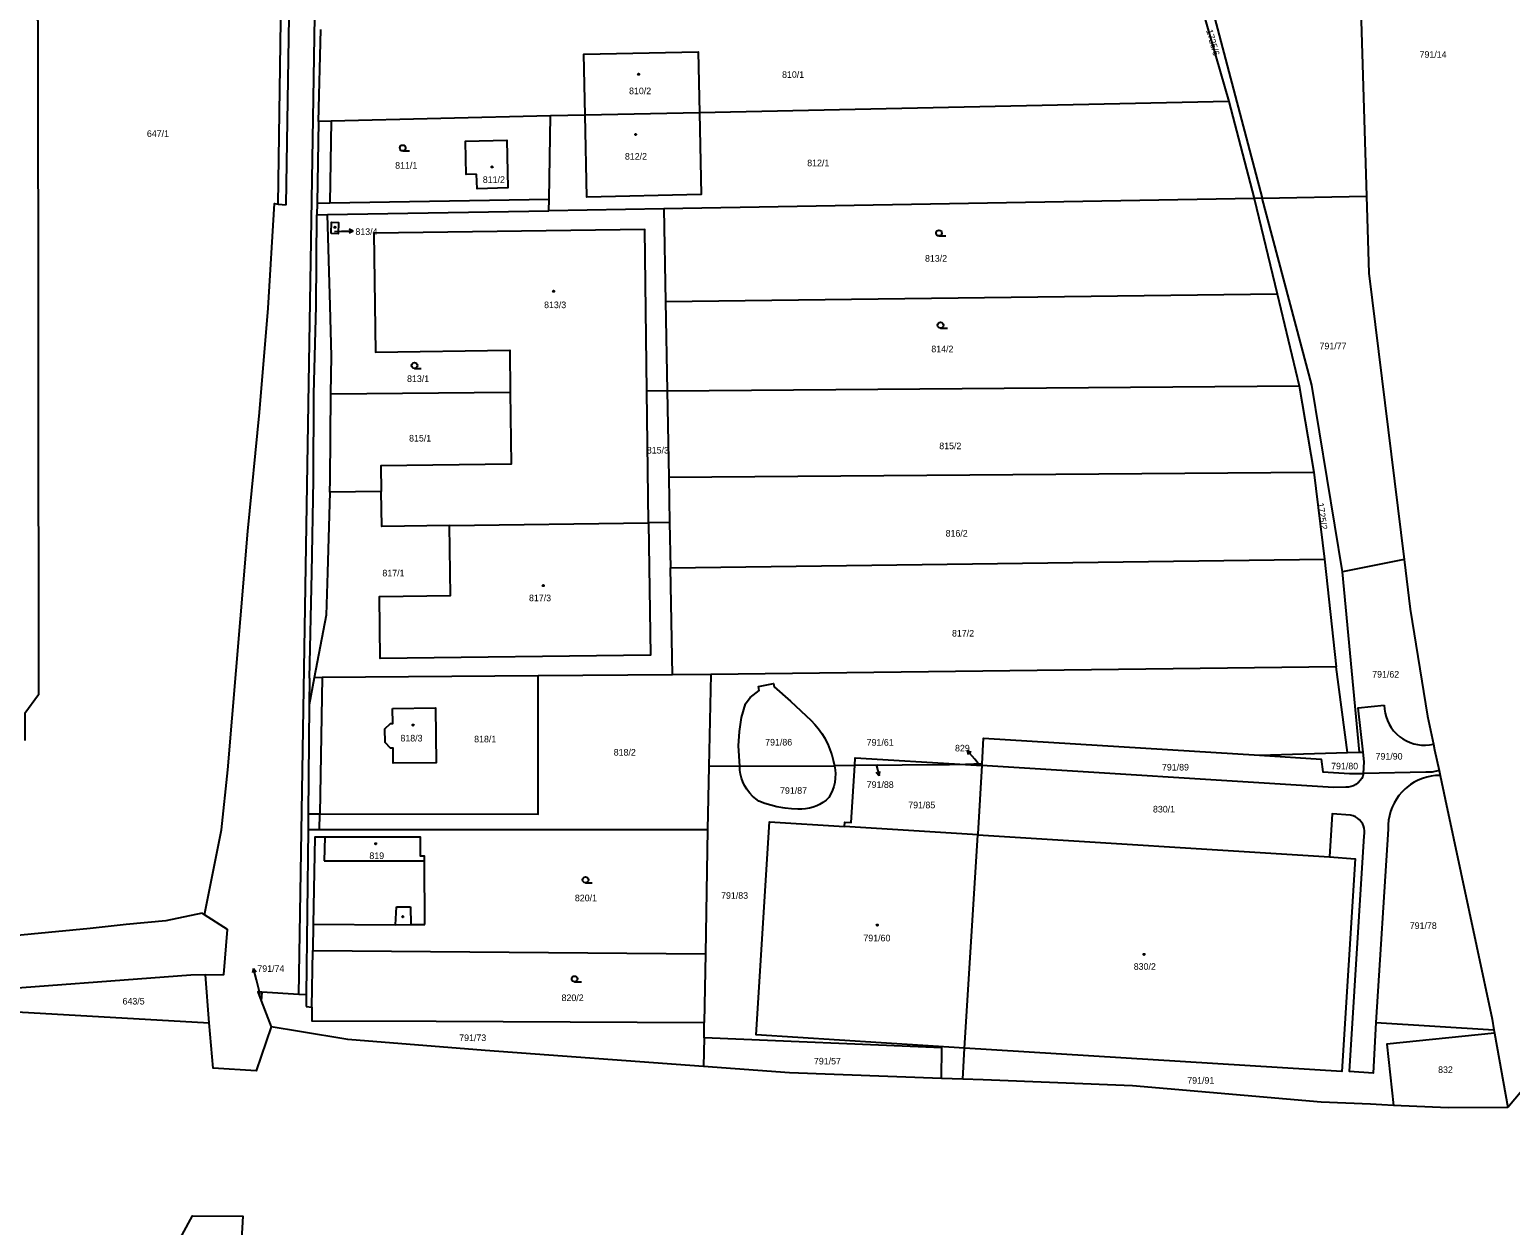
# Model space of a CAD drawing. Extents: x -724107 to -720612, y -1045267 to -1038441.
# Drawn here: x -722617.2 to -722235.9, y -1041870.1 to -1041562.1 of the extents above; entities that cross this region are included whole.
import ezdxf

# ---------------------------------------------------------------- set-up
doc = ezdxf.new("R2010")
doc.units = 0
for name, color, linetype in [('Hranice parcel', 7, 'Continuous'), ('Parcelní čísla', 7, 'Continuous'), ('Pop  PČ popisy', 7, 'Continuous'), ('Vnitřní kresba', 7, 'Continuous'), ('Značky budov', 7, 'Continuous'), ('Značky kultur', 7, 'Continuous')]:
    doc.layers.add(name, color=color, linetype=linetype)

msp = doc.modelspace()

# ---------------------------------------------------------------- linework, layer by layer
at = {"layer": 'Hranice parcel'}
for p, q in [((-722315.07, -1041557.42), (-722308.33, -1041580.65)), ((-722312.48, -1041557.37), (-722299.74, -1041605.52)), ((-722542.76, -1041585.75), (-722542.2, -1041562.06)), ((-722444.69, -1041583.5), (-722474.12, -1041584.11)), ((-722308.33, -1041580.65), (-722444.69, -1041583.5)), ((-722308.33, -1041580.65), (-722301.81, -1041605.56)), ((-722474.12, -1041584.11), (-722483.09, -1041584.3)), ((-722301.81, -1041605.56), (-722453.83, -1041608.27)), ((-722299.74, -1041605.52), (-722301.81, -1041605.56)), ((-722301.81, -1041605.56), (-722295.91, -1041630.17)), ((-722299.74, -1041605.52), (-722272.9, -1041605.04)), ((-722540.46, -1041609.74), (-722483.46, -1041608.8)), ((-722453.83, -1041608.27), (-722483.46, -1041608.8)), ((-722453.83, -1041608.27), (-722453.4, -1041632.16)), ((-722453.4, -1041632.16), (-722295.91, -1041630.17)), ((-722453.4, -1041632.16), (-722452.99, -1041655.19)), ((-722295.91, -1041630.17), (-722290.27, -1041653.85)), ((-722539.65, -1041655.9), (-722493.42, -1041655.52)), ((-722452.99, -1041655.19), (-722458.24, -1041655.23)), ((-722457.8, -1041689.15), (-722458.24, -1041655.23)), ((-722452.99, -1041655.19), (-722290.27, -1041653.85)), ((-722452.99, -1041655.19), (-722452.59, -1041677.4)), ((-722290.27, -1041653.85), (-722286.5, -1041676.06)), ((-722452.59, -1041677.4), (-722286.5, -1041676.06)), ((-722452.59, -1041677.4), (-722452.38, -1041689.08)), ((-722286.5, -1041676.06), (-722283.76, -1041698.49)), ((-722526.64, -1041681.08), (-722539.9, -1041681.26)), ((-722509.08, -1041689.84), (-722457.8, -1041689.15)), ((-722452.38, -1041689.08), (-722457.8, -1041689.15)), ((-722452.38, -1041689.08), (-722452.17, -1041700.77)), ((-722452.17, -1041700.77), (-722283.76, -1041698.49)), ((-722451.67, -1041728.34), (-722452.17, -1041700.77)), ((-722283.76, -1041698.49), (-722280.71, -1041726.24)), ((-722263.22, -1041698.6), (-722279.09, -1041701.81)), ((-722274.75, -1041748.23), (-722279.09, -1041701.81)), ((-722451.67, -1041728.34), (-722486.22, -1041728.6)), ((-722441.75, -1041728.26), (-722451.67, -1041728.34)), ((-722441.75, -1041728.26), (-722442.25, -1041751.9)), ((-722280.71, -1041726.24), (-722441.75, -1041728.26)), ((-722277.82, -1041748.33), (-722280.71, -1041726.24)), ((-722371.92, -1041751.27), (-722376.14, -1041751.4)), ((-722376.14, -1041751.4), (-722371.94, -1041751.66)), ((-722371.94, -1041751.66), (-722371.92, -1041751.27)), ((-722300.49, -1041749.04), (-722277.82, -1041748.33)), ((-722277.82, -1041748.33), (-722274.75, -1041748.23)), ((-722274.75, -1041748.23), (-722273.76, -1041748.2)), ((-722273.48, -1041750.73), (-722273.76, -1041748.2)), ((-722273.66, -1041753.72), (-722273.48, -1041750.73)), ((-722442.25, -1041751.9), (-722442.59, -1041768.19)), ((-722434.31, -1041751.85), (-722442.25, -1041751.9)), ((-722434.31, -1041751.85), (-722409.95, -1041751.71)), ((-722404.69, -1041751.68), (-722409.95, -1041751.71)), ((-722254.24, -1041752.99), (-722253.98, -1041754.22)), ((-722253.98, -1041754.22), (-722252.67, -1041760.31)), ((-722545.43, -1041764.14), (-722545.47, -1041768.15)), ((-722545.47, -1041768.15), (-722545.95, -1041810.78)), ((-722442.59, -1041768.19), (-722443.14, -1041800.17)), ((-722373.04, -1041769.53), (-722407.32, -1041767.39)), ((-722373.04, -1041769.53), (-722282.4, -1041775.2)), ((-722267.33, -1041768.03), (-722270.48, -1041817.83)), ((-722443.14, -1041800.17), (-722443.44, -1041817.83)), ((-722570.93, -1041817.99), (-722571.92, -1041805.59)), ((-722557.35, -1041810.05), (-722557.52, -1041812.28)), ((-722557.52, -1041812.28), (-722554.99, -1041819.01)), ((-722545.95, -1041810.78), (-722545.98, -1041813.71)), ((-722545.98, -1041813.71), (-722544.49, -1041813.88)), ((-722443.51, -1041821.79), (-722443.44, -1041817.83)), ((-722270.48, -1041817.83), (-722240.1, -1041819.75)), ((-722240.1, -1041819.75), (-722239.95, -1041820.6)), ((-722443.51, -1041821.79), (-722443.63, -1041829.2)), ((-722239.95, -1041820.6), (-722236.54, -1041839.78)), ((-722376.9, -1041832.45), (-722376.41, -1041824.46)), ((-722376.9, -1041832.45), (-722382.4, -1041832.25))]:
    msp.add_line(p, q, dxfattribs=at)
for points in [[(-722265.74, -1041433.82), (-722266.73, -1041438.8), (-722270.06, -1041459.03), (-722272.9, -1041484.57), (-722274.08, -1041524.26), (-722274.34, -1041557.03), (-722272.9, -1041605.04)], [(-722618.18, -1041449.99), (-722618.53, -1041555.06), (-722615.08, -1041559.79), (-722614.93, -1041733.5), (-722618.38, -1041738.26), (-722618.4, -1041745.25)], [(-722572.15, -1041790.09), (-722567.78, -1041768.23), (-722566.18, -1041752.78), (-722562.87, -1041713.88), (-722561.01, -1041691.3), (-722557.98, -1041660.77), (-722555.76, -1041633.86), (-722554.15, -1041606.92), (-722553.18, -1041607.03), (-722551.98, -1041524.35)], [(-722474.12, -1041584.11), (-722474.45, -1041568.46), (-722445.02, -1041567.85), (-722444.69, -1041583.5)], [(-722444.69, -1041583.5), (-722444.25, -1041604.59), (-722473.68, -1041605.22), (-722474.12, -1041584.11)], [(-722542.76, -1041585.75), (-722543.17, -1041606.79), (-722543.19, -1041609.79), (-722540.46, -1041609.74)], [(-722483.09, -1041584.3), (-722539.53, -1041585.67), (-722542.76, -1041585.75)], [(-722483.46, -1041608.8), (-722483.36, -1041605.77), (-722483.09, -1041584.3)], [(-722502.08, -1041599.34), (-722504.81, -1041599.39), (-722504.88, -1041595.26), (-722504.96, -1041590.81), (-722494.26, -1041590.57), (-722494.08, -1041602.88), (-722501.97, -1041603.09), (-722502.08, -1041599.34)], [(-722279.09, -1041701.81), (-722287.01, -1041653.65), (-722299.74, -1041605.52)], [(-722272.9, -1041605.04), (-722272.3, -1041624.85), (-722263.22, -1041698.6)], [(-722539.65, -1041655.9), (-722539.47, -1041646.18), (-722539.76, -1041633.25), (-722540.46, -1041609.74)], [(-722539.5, -1041614.63), (-722539.43, -1041611.69), (-722537.67, -1041611.75), (-722537.76, -1041614.68), (-722539.5, -1041614.63)], [(-722458.24, -1041655.23), (-722458.79, -1041613.63), (-722528.52, -1041614.54), (-722528.11, -1041645.16), (-722493.55, -1041644.65), (-722493.42, -1041655.52)], [(-722539.9, -1041681.26), (-722539.81, -1041678.1), (-722539.65, -1041655.9)], [(-722493.42, -1041655.52), (-722493.21, -1041674.06), (-722526.75, -1041674.5), (-722526.64, -1041681.08)], [(-722539.9, -1041681.26), (-722540.52, -1041701.96), (-722540.85, -1041712.96), (-722543.88, -1041729.05)], [(-722509.08, -1041689.84), (-722526.49, -1041690.08), (-722526.64, -1041681.08)], [(-722457.8, -1041689.15), (-722457.31, -1041723.25), (-722526.89, -1041724.1), (-722527.12, -1041708.12), (-722508.84, -1041707.86), (-722509.08, -1041689.84)], [(-722263.22, -1041698.6), (-722261.65, -1041711.4), (-722257.23, -1041738.96), (-722255.69, -1041746.18)], [(-722545.43, -1041764.14), (-722542.47, -1041764.14), (-722486.24, -1041764.17), (-722486.22, -1041728.6)], [(-722486.22, -1041728.6), (-722541.83, -1041729.03), (-722543.88, -1041729.05)], [(-722543.88, -1041729.05), (-722545.19, -1041736.01), (-722545.43, -1041764.14)], [(-722434.31, -1041751.85), (-722434.6, -1041746.62), (-722434.38, -1041742.93), (-722433.87, -1041739.28), (-722432.83, -1041735.75), (-722431.62, -1041734.11), (-722429.31, -1041732.3), (-722429.5, -1041731.27), (-722425.64, -1041730.54), (-722425.48, -1041731.38), (-722421.22, -1041735.09), (-722415.96, -1041740.08)], [(-722273.76, -1041748.2), (-722275.05, -1041736.8), (-722268.34, -1041736.15)], [(-722268.34, -1041736.15), (-722268.28, -1041737.17), (-722268.12, -1041738.17), (-722267.87, -1041739.16), (-722267.52, -1041740.11), (-722267.08, -1041741.03), (-722266.55, -1041741.9), (-722265.93, -1041742.71), (-722265.24, -1041743.46), (-722265.12, -1041743.58), (-722264.35, -1041744.24), (-722263.52, -1041744.83), (-722262.63, -1041745.33), (-722261.7, -1041745.74), (-722260.73, -1041746.06), (-722259.74, -1041746.28), (-722258.73, -1041746.41), (-722257.71, -1041746.43), (-722256.69, -1041746.35), (-722255.69, -1041746.18)], [(-722523.7, -1041736.96), (-722512.69, -1041736.84), (-722512.53, -1041750.96), (-722523.53, -1041751.09), (-722523.61, -1041747.18), (-722524.23, -1041747.17), (-722525.64, -1041745.76), (-722525.72, -1041742.24), (-722524.28, -1041740.85), (-722523.68, -1041740.85), (-722523.7, -1041736.96)], [(-722415.96, -1041740.08), (-722414.96, -1041741.13), (-722414.04, -1041742.24), (-722413.2, -1041743.42), (-722412.44, -1041744.65), (-722412.3, -1041744.9), (-722411.64, -1041746.19), (-722411.08, -1041747.52), (-722410.6, -1041748.89), (-722410.23, -1041750.29), (-722409.95, -1041751.71)], [(-722371.92, -1041751.27), (-722371.51, -1041744.61), (-722300.49, -1041749.04)], [(-722255.69, -1041746.18), (-722255.38, -1041747.63), (-722254.24, -1041752.99)], [(-722404.69, -1041751.68), (-722404.56, -1041749.65), (-722376.14, -1041751.4)], [(-722376.14, -1041751.4), (-722380.32, -1041751.53), (-722404.69, -1041751.68)], [(-722300.49, -1041749.04), (-722284.57, -1041750.03), (-722284.18, -1041753.3), (-722277.31, -1041753.68), (-722275.83, -1041753.76), (-722274.24, -1041753.73), (-722273.66, -1041753.72)], [(-722409.95, -1041751.71), (-722409.78, -1041752.75), (-722409.7, -1041753.8), (-722409.72, -1041754.85), (-722409.73, -1041754.96), (-722409.86, -1041756), (-722410.1, -1041757.03), (-722410.43, -1041758.03), (-722410.85, -1041758.99), (-722411.36, -1041759.91), (-722412.1, -1041760.59), (-722412.91, -1041761.19), (-722413.77, -1041761.71), (-722414.47, -1041762.05), (-722415.41, -1041762.42), (-722416.38, -1041762.68), (-722417.37, -1041762.85), (-722418.37, -1041762.92), (-722419.38, -1041762.89), (-722420.99, -1041762.83), (-722422.59, -1041762.68), (-722423.2, -1041762.59), (-722424.78, -1041762.3), (-722426.34, -1041761.91), (-722427.87, -1041761.42), (-722429.37, -1041760.84), (-722430.21, -1041760.24), (-722431, -1041759.56), (-722431.71, -1041758.81), (-722432.35, -1041757.99), (-722432.53, -1041757.72), (-722433.06, -1041756.83), (-722433.5, -1041755.89), (-722433.85, -1041754.92), (-722434.1, -1041753.91), (-722434.26, -1041752.89), (-722434.31, -1041751.85)], [(-722407.32, -1041767.39), (-722407.26, -1041766.26), (-722405.66, -1041766.38), (-722404.69, -1041751.68)], [(-722371.94, -1041751.66), (-722373.02, -1041769.27), (-722373.04, -1041769.53)], [(-722278.22, -1041757.26), (-722281.43, -1041757.32), (-722371.94, -1041751.66)], [(-722273.66, -1041753.72), (-722273.86, -1041754.37), (-722274.15, -1041754.97), (-722274.53, -1041755.53), (-722274.99, -1041756.03), (-722275.11, -1041756.14), (-722275.65, -1041756.54), (-722276.25, -1041756.86), (-722276.88, -1041757.09), (-722277.55, -1041757.23), (-722278.22, -1041757.26)], [(-722254.24, -1041752.99), (-722256, -1041753.35), (-722257.64, -1041753.41), (-722273.66, -1041753.72)], [(-722253.98, -1041754.22), (-722255.13, -1041754.27), (-722256.28, -1041754.42), (-722257.41, -1041754.67), (-722258.51, -1041755.01), (-722259.58, -1041755.45), (-722260.61, -1041755.98), (-722261.59, -1041756.59), (-722262.51, -1041757.29), (-722262.98, -1041757.71), (-722263.8, -1041758.52), (-722264.55, -1041759.4), (-722265.21, -1041760.35), (-722265.8, -1041761.35), (-722266.29, -1041762.39), (-722266.69, -1041763.47), (-722267, -1041764.59), (-722267.21, -1041765.72), (-722267.32, -1041766.88), (-722267.33, -1041768.03)], [(-722252.67, -1041760.31), (-722240.58, -1041816.98), (-722240.1, -1041819.75)], [(-722376.41, -1041824.46), (-722430.08, -1041821.03), (-722426.65, -1041766.18), (-722407.32, -1041767.39)], [(-722277.01, -1041764.46), (-722281.73, -1041764.15), (-722282.4, -1041775.2)], [(-722273.51, -1041769.82), (-722273.41, -1041769.16), (-722273.41, -1041768.49), (-722273.51, -1041767.84), (-722273.7, -1041767.2), (-722273.9, -1041766.76), (-722274.26, -1041766.2), (-722274.69, -1041765.69), (-722275.19, -1041765.26), (-722275.76, -1041764.9), (-722276.37, -1041764.63), (-722277.01, -1041764.46)], [(-722545.47, -1041768.15), (-722542.54, -1041768.14), (-722442.59, -1041768.19)], [(-722515.43, -1041792.58), (-722515.48, -1041776.23), (-722515.47, -1041774.98), (-722516.51, -1041774.99), (-722516.5, -1041770.13), (-722541.19, -1041770.09), (-722543.75, -1041770.09), (-722544.13, -1041792.57), (-722522.98, -1041792.68), (-722519.05, -1041792.63), (-722515.43, -1041792.58)], [(-722376.41, -1041824.46), (-722376.33, -1041823.18), (-722373.04, -1041769.53)], [(-722270.48, -1041817.83), (-722271.22, -1041830.88), (-722277.29, -1041830.53), (-722273.51, -1041769.82)], [(-722572.15, -1041790.09), (-722572.74, -1041789.71), (-722582.1, -1041791.68), (-722592.36, -1041792.63), (-722601.62, -1041793.62), (-722636.53, -1041797.02), (-722697.04, -1041802.03), (-722736.46, -1041801.53), (-722782.47, -1041798.74), (-722864.18, -1041795.53), (-722887.81, -1041795.13), (-722950.17, -1041789.44), (-722986.65, -1041786.31), (-723038.66, -1041784.3), (-723089.92, -1041782.77), (-723094.54, -1041778.33), (-723095.52, -1041777.18)], [(-722282.4, -1041775.2), (-722275.87, -1041775.67), (-722279.29, -1041830.52), (-722376.41, -1041824.46)], [(-722571.92, -1041805.59), (-722567.17, -1041805.48), (-722566.22, -1041793.95), (-722572.15, -1041790.09)], [(-722544.49, -1041813.88), (-722544.24, -1041799.36), (-722443.14, -1041800.17)], [(-722571.92, -1041805.59), (-722575.67, -1041805.69), (-722633.05, -1041809.97), (-722652.84, -1041811.22), (-722679.23, -1041813.23), (-722679.21, -1041814.75)], [(-722557.35, -1041810.05), (-722558.38, -1041809.98), (-722557.52, -1041812.28)], [(-722545.95, -1041810.78), (-722547.85, -1041810.66), (-722557.35, -1041810.05)], [(-722679.21, -1041814.75), (-722631.41, -1041814.8), (-722620.47, -1041815.12), (-722570.93, -1041817.99)], [(-722544.49, -1041813.88), (-722544.55, -1041817.4), (-722512.51, -1041817.54), (-722443.44, -1041817.83)], [(-722554.99, -1041819.01), (-722558.86, -1041830.28), (-722569.93, -1041829.62), (-722570.93, -1041817.99)], [(-722443.63, -1041829.2), (-722499.89, -1041825.11), (-722535.21, -1041822.28), (-722547.65, -1041820.22), (-722554.99, -1041819.01)], [(-722382.4, -1041832.25), (-722382.31, -1041824.43), (-722443.51, -1041821.79)], [(-722239.95, -1041820.6), (-722267.72, -1041823.45), (-722265.92, -1041839.22)], [(-722382.4, -1041832.25), (-722421.53, -1041830.81), (-722443.63, -1041829.2)], [(-722265.92, -1041839.22), (-722268.96, -1041839.08), (-722271.9, -1041838.94), (-722284.61, -1041838.35), (-722333.14, -1041834.17), (-722371.65, -1041832.64), (-722376.9, -1041832.45)], [(-722214.16, -1041838.45), (-722210.51, -1041854.4), (-722230.06, -1041853.88), (-722232.25, -1041846.67), (-722232.88, -1041835.47), (-722236.54, -1041839.78)], [(-722236.54, -1041839.78), (-722251.92, -1041839.87), (-722265.92, -1041839.22)], [(-722580.09, -1041876.52), (-722575.26, -1041867.66), (-722562.3, -1041867.74), (-722562.79, -1041876.81), (-722559.17, -1041879.54)]]:
    msp.add_lwpolyline(points, dxfattribs=at)
at = {"layer": 'Pop  PČ popisy'}
for p, q in [((-722538.69, -1041614.07), (-722536.88, -1041614.03)), ((-722536.88, -1041614.03), (-722533.88, -1041613.98)), ((-722533.88, -1041613.98), (-722534.89, -1041613.49)), ((-722533.88, -1041613.98), (-722534.87, -1041614.5)), ((-722373.8, -1041750.07), (-722375.73, -1041747.77)), ((-722375.73, -1041747.77), (-722374.7, -1041748.22)), ((-722375.73, -1041747.77), (-722375.47, -1041748.86)), ((-722399.18, -1041751.42), (-722398.45, -1041754.33)), ((-722372.62, -1041751.49), (-722373.8, -1041750.07)), ((-722398.45, -1041754.33), (-722399.18, -1041753.48)), ((-722398.45, -1041754.33), (-722398.21, -1041753.24)), ((-722559.56, -1041803.97), (-722559.78, -1041805.07)), ((-722558.78, -1041806.87), (-722559.56, -1041803.97)), ((-722559.56, -1041803.97), (-722558.81, -1041804.81)), ((-722557.79, -1041810.64), (-722558.78, -1041806.87))]:
    msp.add_line(p, q, dxfattribs=at)
at = {"layer": 'Vnitřní kresba'}
for p, q in [((-722547.85, -1041810.66), (-722541.2, -1041403.77)), ((-722551.15, -1041607.26), (-722547.81, -1041404.83)), ((-722539.53, -1041585.67), (-722539.88, -1041606.73)), ((-722539.88, -1041606.73), (-722483.36, -1041605.77)), ((-722553.18, -1041607.03), (-722551.15, -1041607.26)), ((-722543.42, -1041633.3), (-722543.19, -1041609.79)), ((-722543.17, -1041606.79), (-722539.88, -1041606.73)), ((-722544.02, -1041655.94), (-722543.42, -1041633.3)), ((-722544.12, -1041678.13), (-722544.02, -1041655.94)), ((-722544.49, -1041702.01), (-722544.12, -1041678.13)), ((-722545.13, -1041729.16), (-722544.49, -1041702.01)), ((-722545.13, -1041729.16), (-722545.19, -1041736.01)), ((-722541.83, -1041729.03), (-722542.47, -1041764.14)), ((-722542.54, -1041768.14), (-722542.47, -1041764.14)), ((-722541.19, -1041770.09), (-722541.35, -1041776.25)), ((-722541.35, -1041776.25), (-722515.48, -1041776.23)), ((-722522.98, -1041792.68), (-722522.74, -1041788.1)), ((-722522.74, -1041788.1), (-722519.07, -1041788.05)), ((-722519.07, -1041788.05), (-722519.05, -1041792.63)), ((-722544.13, -1041792.57), (-722544.24, -1041799.36))]:
    msp.add_line(p, q, dxfattribs=at)
at = {"layer": 'Značky budov'}
for centre in [(-722460.38, -1041573.59), (-722461.13, -1041589.12), (-722498.09, -1041597.48), (-722538.56, -1041613), (-722482.27, -1041629.51), (-722484.92, -1041705.3), (-722518.43, -1041741.24), (-722528.05, -1041771.82), (-722521.08, -1041790.6), (-722398.92, -1041792.77), (-722330.18, -1041800.34)]:
    msp.add_circle(centre, 0.175, dxfattribs=at)
at = {"layer": 'Značky kultur'}
for p, q in [((-722521.11, -1041593.34), (-722519.36, -1041593.34)), ((-722383.01, -1041615.25), (-722381.26, -1041615.25)), ((-722382.6, -1041639), (-722380.85, -1041639)), ((-722518.09, -1041649.38), (-722516.34, -1041649.38)), ((-722474.05, -1041781.88), (-722472.3, -1041781.88)), ((-722476.85, -1041807.4), (-722475.1, -1041807.4))]:
    msp.add_line(p, q, dxfattribs=at)
for centre in [(-722521.11, -1041592.59), (-722383.01, -1041614.5), (-722382.6, -1041638.25), (-722518.09, -1041648.63), (-722474.05, -1041781.13), (-722476.85, -1041806.65)]:
    msp.add_circle(centre, 0.75, dxfattribs=at)

# ---------------------------------------------------------------- texts
at = {"layer": 'Parcelní čísla'}
for s, rotation, p in [('1725/6', 286, (-722314.23, -1041562.31)), ('1725/2', 278, (-722285.62, -1041684.12))]:
    msp.add_text(s, height=1.7, rotation=rotation, dxfattribs=at).set_placement(p)
for s, p in [('791/14', (-722259.24, -1041569.35)), ('810/1', (-722423.42, -1041574.52)), ('810/2', (-722462.82, -1041578.73)), ('647/1', (-722586.99, -1041589.74)), ('812/2', (-722463.89, -1041595.6)), ('811/1', (-722523.05, -1041597.93)), ('812/1', (-722416.94, -1041597.29)), ('811/2', (-722500.48, -1041601.59)), ('813/4', (-722533.29, -1041614.99)), ('813/2', (-722386.61, -1041621.88)), ('813/3', (-722484.7, -1041633.85)), ('814/2', (-722384.98, -1041645.21)), ('791/77', (-722285.01, -1041644.45)), ('813/1', (-722519.99, -1041652.88)), ('815/1', (-722519.47, -1041668.2)), ('815/3', (-722458.24, -1041671.3)), ('815/2', (-722382.93, -1041670.18)), ('816/2', (-722381.3, -1041692.69)), ('817/1', (-722526.34, -1041702.95)), ('817/3', (-722488.59, -1041709.34)), ('817/2', (-722379.66, -1041718.44)), ('791/62', (-722271.45, -1041729.01)), ('818/3', (-722521.69, -1041745.47)), ('818/1', (-722502.71, -1041745.71)), ('818/2', (-722466.77, -1041749.11)), ('791/86', (-722427.77, -1041746.51)), ('791/61', (-722401.63, -1041746.56)), ('829', (-722378.88, -1041748.04)), ('791/89', (-722325.59, -1041752.95)), ('791/80', (-722282.02, -1041752.67)), ('791/90', (-722270.58, -1041750.14)), ('791/87', (-722423.94, -1041758.96)), ('791/88', (-722401.62, -1041757.44)), ('791/85', (-722390.92, -1041762.69)), ('830/1', (-722327.9, -1041763.76)), ('819', (-722529.69, -1041775.76)), ('820/1', (-722476.77, -1041786.63)), ('791/83', (-722439.12, -1041786)), ('791/78', (-722261.77, -1041793.76)), ('791/60', (-722402.48, -1041796.96)), ('791/74', (-722558.54, -1041804.82)), ('830/2', (-722332.85, -1041804.29)), ('643/5', (-722593.26, -1041813.23)), ('820/2', (-722480.2, -1041812.35)), ('791/73', (-722506.56, -1041822.65)), ('791/57', (-722415.21, -1041828.67)), ('832', (-722254.47, -1041830.87)), ('791/91', (-722319.07, -1041833.63))]:
    msp.add_text(s, height=1.7, dxfattribs=at).set_placement(p)

doc.saveas('drawing.dxf')
